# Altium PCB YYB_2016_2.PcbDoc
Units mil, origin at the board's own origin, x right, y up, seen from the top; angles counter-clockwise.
Board outline 590 x 11950 mil, 2 copper layers (Top Layer, Bottom Layer); 76 components, 58 nets, 220 pads, 97 vias.
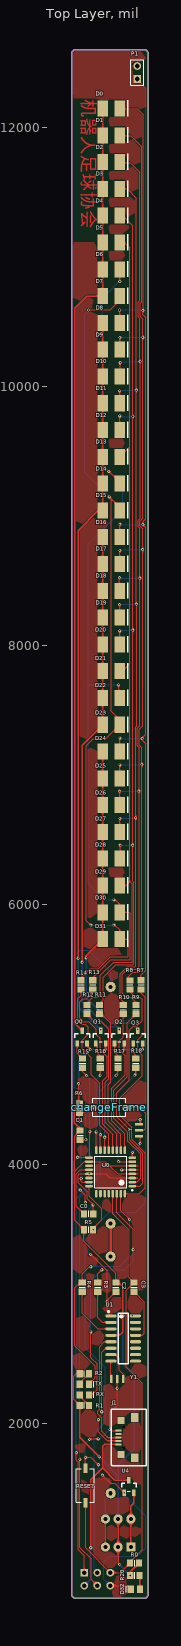
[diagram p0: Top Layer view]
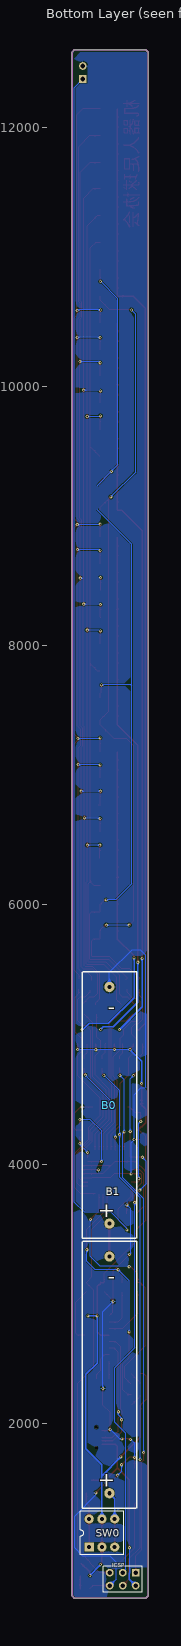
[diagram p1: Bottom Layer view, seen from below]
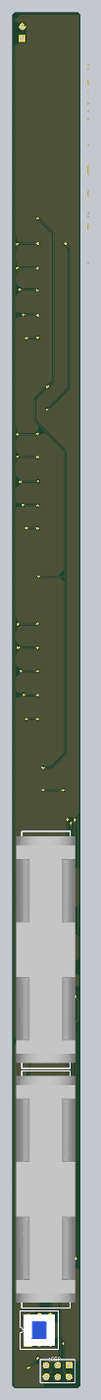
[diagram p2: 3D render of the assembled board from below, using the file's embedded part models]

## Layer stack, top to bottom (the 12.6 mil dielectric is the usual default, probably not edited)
Top Solder: solder mask 0.4, Solder Resist, Dk 3.5
Top Layer: signal copper 1.4
Dielectric 1: dielectric 12.6, FR-4, Dk 4.8
Bottom Layer: signal copper 1.4
Bottom Solder: solder mask 0.4, Solder Resist, Dk 3.5

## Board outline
4930,670 4930,12580 4950,12600 5500,12600 5520,12580 5520,670 5500,650 4950,650

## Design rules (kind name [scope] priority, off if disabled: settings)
Clearance [All] p1: gap=7
PolygonConnect [All] p1: connectstyle=Relief reliefconductorwidth=10 reliefentries=4 polygonreliefangle="90 Angle" airgapwidth=10
RoutingVias [All] p1: holewidth=11.81 width=31.5 viastyle="Through Hole" minholewidth=11.81 minwidth=23.62 maxholewidth=248.03 maxwidth=50
SolderMaskExpansion [All] p1: expansion=4
Width [All] p1: maxlimit=30 minlimit=6 preferedwidth=10
30 further rules are at their usual default settings.

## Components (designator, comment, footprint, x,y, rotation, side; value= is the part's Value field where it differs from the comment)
B0 "Battery" BAT 5230,4470 r0 bottom locked
B1 "Battery" BAT 5230,2389 r0 bottom locked
C0 "" 6-0805_N 5060,3616 r180 top
C1 "Cap" 6-0805_N 4994,4224 r90 top
C2 "Cap" 6-0805_N 5270,3050 r90 top
C3 "Cap" 6-0805_N 5410,3050 r90 top
changeFrame "SW-PB" KEY_SODFL_2-LEADS 5220,4440 r180 top
D0 "" LED_3528 5234.06,12146.77 r0 top
D1 "" LED_3528 5234.06,11940 r0 top
D2 "" LED_3528 5234.06,11733.23 r0 top
D3 "" LED_3528 5234.06,11526.45 r0 top
D4 "" LED_3528 5234.06,11319.68 r0 top
D5 "" LED_3528 5234.06,11112.9 r0 top
D6 "" LED_3528 5234.06,10906.13 r0 top
D7 "" LED_3528 5234.06,10699.36 r0 top
D8 "" LED_3528 5234.06,10492.58 r0 top
D9 "" LED_3528 5234.06,10285.81 r0 top
D10 "" LED_3528 5234.06,10079.03 r0 top
D11 "" LED_3528 5234.06,9872.26 r0 top
D12 "" LED_3528 5234.06,9665.48 r0 top
D13 "" LED_3528 5234.06,9458.71 r0 top
D14 "" LED_3528 5234.06,9251.94 r0 top
D15 "" LED_3528 5234.06,9045.16 r0 top
D16 "" LED_3528 5234.06,8838.39 r0 top
D17 "" LED_3528 5234.06,8631.61 r0 top
D18 "" LED_3528 5234.06,8424.84 r0 top
D19 "" LED_3528 5234.06,8218.07 r0 top
D20 "" LED_3528 5234.06,8011.29 r0 top
D21 "" LED_3528 5234.06,7804.52 r0 top
D22 "" LED_3528 5234.06,7597.74 r0 top
D23 "" LED_3528 5234.06,7390.97 r0 top
D24 "" LED_3528 5234.06,7184.2 r0 top
D25 "" LED_3528 5234.06,6977.42 r0 top
D26 "" LED_3528 5234.06,6770.65 r0 top
D27 "" LED_3528 5234.06,6563.87 r0 top
D28 "" LED_3528 5234.06,6357.1 r0 top
D29 "" LED_3528 5234.06,6150.33 r0 top
D30 "" LED_3528 5234.06,5943.55 r0 top
D31 "" LED_3528 5234.06,5736.78 r0 top
D32 "LED" LED_0805 5420.37,719 r180 top
ICSP "ICSP" HDR2X3 5027,847 r0 bottom
J1 "USB_MINI" MICRO_USB 5290,1890 r90 top
P1 "Header 2" HDR1X2 5435,12375 r90 top
Q0 "PNP" PNP_SOT_23 5010,4980 r270 top
Q1 "PNP" PNP_SOT_23 5153.33,4980 r270 top
Q2 "PNP" PNP_SOT_23 5296.67,4980 r270 top
Q3 "PNP" PNP_SOT_23 5440,4980 r270 top
R0 "" 6-0805_N 5414,921 r180 top
R1 "Res1" 6-0805_N 5027,2138 r0 top
R2 "Res1" 6-0805_N 5027,2382 r0 top
R3 "Res1" 6-0805_N 5130,3050 r270 top
R4 "Res1" 6-0805_N 5010,3050 r270 top
R5 "Res1" 6-0805_N 5059,3493 r180 top
R6 "Res1" 6-0805_N 4988,4432 r90 top
R7 "Res1" 6-0805_N 5465,5384 r270 top
R8 "Res1" 6-0805_N 5378,5383 r270 top
R9 "Res1" 6-0805_N 5425,5193 r270 top
R10 "Res1" 6-0805_N 5327,5193 r270 top
R11 "Res1" 6-0805_N 5145,5193 r270 top
R12 "Res1" 6-0805_N 5047,5193 r270 top
R13 "Res1" 6-0805_N 5092,5384 r270 top
R14 "Res1" 6-0805_N 5001,5384 r270 top
R15 "Res1" 6-0805_N 5012,4779 r270 top
R16 "Res1" 6-0805_N 5149,4779 r270 top
R17 "Res1" 6-0805_N 5286,4779 r270 top
R18 "Res1" 6-0805_N 5423,4779 r270 top
R20 "Res1" 6-0805_N 5416.43,825 r180 top
RESET "SW-PB" KEY_SODFL_2-LEADS 5035,1520 r270 top
RX "" LED_0805 5027,2219 r0 top
SW0 "SelfLockSW" KEY_ZS_8*8 5317,1153 r90 bottom
TX "" LED_0805 5027,2301 r0 top
U0 "ATMEL328P" "TQFP 32" 5230,3940 r180 top
U1 "CH340B" SOP16 5350,2530 r0 top
U4 "SC662K" SOT-23 5371,1512 r270 top
Y "8M" XTAL 5471,4262 r0 top
Y1 "12M" XTAL 5280,2319 r270 top

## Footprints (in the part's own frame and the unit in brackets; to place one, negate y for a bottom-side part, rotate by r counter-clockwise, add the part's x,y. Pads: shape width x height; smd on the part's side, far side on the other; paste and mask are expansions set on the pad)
6-0805_N [mm] "Chip Resistor, Body 2.0x1.2mm, IPC Medium Density"
  rect 1.2x1.4 smd: 1(-0.9,0) 2(0.9,0)
  silkscreen extent 0,-0.6 0,0.6, body extent -1.07,-0.7 1.07,0.7, height 0.7
BAT [mm]
  round 2 hole 0.8: 1(0,23.6) 2(0,-22.8)
  silkscreen extent -5.4,-25.8 5.3,26.5, body extent -6.5,-24.7 6.5,25.3, height 13.75
HDR1X2 [mm] "Connector; Header; 2 Position"
  rect 1.5x1.5 hole 0.9: 1(0,0)
  round 1.5 hole 0.9: 2(2.54,0)
  silkscreen extent -1.27,-1.27 3.81,1.27
HDR2X3 [mm] "Connector; Header; 3x2 Position"
  rect 1.5x1.5 hole 0.9: 1(0,0)
  round 1.5 hole 0.9: 2(0,2.54) 3(2.54,0) 4(2.54,2.54) 5(5.08,0) 6(5.08,2.54)
  silkscreen extent -1.27,-1.27 6.35,3.81
KEY_SODFL_2-LEADS [mm] "SODFL, 2-Leads, Body 3.25x8.00mm, IPC Medium Density"
  rect 1.85x0.85 smd: 1(-3.375,0) 2(3.375,0)
  silkscreen extent -3.25,-1.75 3.25,1.75, body extent -4,-1.8 4,1.91, height 2.5
KEY_ZS_8*8 [mm]
  rect 1.8x1.8 hole 0.8: 1(-2.75,1.75)
  round 1.8 hole 0.8: 2(-2.75,-0.75) 3(-2.75,-3.25) 4(2.75,-3.25) 5(2.75,-0.75) 6(2.75,1.75)
  silkscreen extent -4.25,-5 4.25,3.5, body extent -3.5,-4.26 3.5,2.74, height 13
LED_0805 [mm] "Chip LED  Body 2.0x1.2mm, IPC Medium Density"
  rect 1.2x1.4 smd: 1(-0.9,0) 2(0.9,0)
  silkscreen extent 1.8,-0.6 1.8,0.6, body extent -1.07,-0.7 1.07,0.7, height 0.7
LED_3528 [mm] "Chip Diode, 2-Leads, Body 5.00x3.00mm, IPC Medium Density"
  rect 2x3.15 smd: 1(-1.675,0) 2(1.675,0)
  silkscreen extent 3.2,-1.5 3.2,1.6, body extent -2.5,-1.5 2.5,1.5, height 2
MICRO_USB [mm]
  round 0.5 hole 0.5: 0(-2.032,-1.016) 0(2.032,-1.016)
  rect 0.4x1.2 smd: 1(-1.333,0) 2(-0.667,0) 3(0,0) 4(0.667,0) 5(1.333,0)
  rect 1.4x1.4 smd: 6(-3.302,-0.508) 7(3.302,-0.508)
  rect 1.7x1.5 smd: 8(-3.937,-3.175) 9(3.937,-3.175)
  silkscreen extent -5.54,-5.46 5.59,1.4, body extent -4.4,-5.72 4.4,0.02, height 2.71
PNP_SOT_23 [mm]
  rect 1.25x0.7 smd: 1(1.25,-0.95) 2(1.25,0.95) 3(-1.25,0)
  silkscreen extent -0.65,-1.46 0.9,1.46, body extent -1.5,-1.5 1.5,1.5, height 1.3
SOP16 [mm] "CH340G"
  oval 2.2x0.6 smd: 1(-3,7.595) 2(-3,6.325) 3(-3,5.055) 4(-3,3.785) 5(-3,2.515) 6(-3,1.245) 7(-3,-0.025) 8(-3,-1.295) 9(1.8,-1.295) 10(1.8,-0.025) 11(1.8,1.245) 12(1.8,2.515) 13(1.8,3.785) 14(1.8,5.055) 15(1.8,6.325) 16(1.8,7.595)
  silkscreen extent -3.65,-1.83 0.4,8.6, body extent -3.68,-1.78 2.51,8.13, height 1.7
SOT-23 [mm]
  rect 1.25x0.7 smd: 1(1.25,-0.95) 2(1.25,0.95) 3(-1.25,0)
  silkscreen extent -0.65,-1.46 0.9,1.46, body extent -1.5,-1.5 1.5,1.5, height 1.3
"TQFP 32" [mm] "ATMEL 328P"
  oval 1.5x0.5 smd: 1(-4.25,2.8) 2(-4.25,2) 3(-4.25,1.2) 4(-4.25,0.4) 5(-4.25,-0.4) 6(-4.25,-1.2) 7(-4.25,-2) 8(-4.25,-2.8) 17(4.25,-2.8) 18(4.25,-2) 19(4.25,-1.2) 20(4.25,-0.4) 21(4.25,0.4) 22(4.25,1.2) 23(4.25,2) 24(4.25,2.8)
  oval 0.5x1.5 smd: 9(-2.8,-4.25) 10(-2,-4.25) 11(-1.2,-4.25) 12(-0.4,-4.25) 13(0.4,-4.25) 14(1.2,-4.25) 15(2,-4.25) 16(2.8,-4.25) 25(2.8,4.25) 26(2,4.25) 27(1.2,4.25) 28(0.4,4.25) 29(-0.4,4.25) 30(-1.2,4.25) 31(-2,4.25) 32(-2.8,4.25)
  silkscreen extent -4.38,-3.1 3.1,3.72, body extent -4.57,-4.57 4.57,4.57, height 1.62
XTAL [mm] "Chip Array, ConvexE, 6-Leads, Pitch 1.20mm,  Body 3.20x1.50mm,  IPC Medium Density"
  rect 1.6x0.5 smd: 1(-0.6,1.2) 2(-0.6,0) 3(-0.6,-1.2)

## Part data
C0: library part Cap, "Capacitor"
C1 C2 C3: "Capacitor"
changeFrame RESET: "Switch"
D0 D1 D2 D3 D4 D5 D6 D7 D8 D9 D10 D11 D12 D13 D14 D15 D16 D17 D18 D19 D20 D21 D22 D23 D24 D25 D26 D27 D28 D29 D30 D31 RX TX: library part LED
P1: "Header, 2-Pin"
Q0 Q1 Q2 Q3: "PNP Transistor"
R0: library part Res1, "Resistor"
R1 R2 R3 R4 R5 R6 R7 R8 R9 R10 R11 R12 R13 R14 R15 R16 R17 R18 R20: "Resistor"
SW0: library part SelfLockSwitch, "自锁开关"
U0: library part ATMEL-328P
U1: "usb to uart"
U4: library part SC662k-3.3V, "3.3V 稳压芯片"
Y Y1: library part XTAL

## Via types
v1: diameter 23.62, hole 11.81, Top Layer to Bottom Layer, 97 vias

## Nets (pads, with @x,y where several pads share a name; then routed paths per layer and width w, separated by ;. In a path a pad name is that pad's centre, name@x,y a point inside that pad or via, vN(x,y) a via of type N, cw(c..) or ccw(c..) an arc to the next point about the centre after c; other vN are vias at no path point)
3.3V: C1.2 C2.2 Q0.2 Q1.2 Q2.2 Q3.2 R0.1 R1.1 R2.1 R5.2 R6.2 R20.2 SW0.2 SW0.5 U0.4 U0.6 U0.18 U1.4 U1.16 | length 7258.4
  Top Layer w7: R1.1 4945.5,2184.07 4945.5,2363.5 4964,2382 R2.1 ; C1.2 4951,4216.43 4951,3945 ; C2.2 5270,3159 5023.57,3405.43 R5.2 4951,3565.57 4951,3945 ; 5441,3986 5439.76,3987.24 U0.6 5219.76,3987.24 ; 5443,3925 5442.25,3924.25 U0.4 5282.75,3924.25 5219.76,3987.24 ; 4951,3945 5024.74,4018.74 U0.18 5188.26,4018.74 5219.76,3987.24
  Top Layer w10: R6.2@4970.43,4467.43 4990.72,4467.43 4948.44,4425.16 4948.44,4320.56 5005.57,4263.43 C1.2@5018,4263.43 ; v1(4982,4622) 4982,4481.43 4978,4477.43 R6.2 ; R1.1 4991.57,1890.43 v1(5142,1740) ; Q0.2 5047.4,4912.6 5071,4889 v1(5071,4884) ; v1(5190.73,4885.27) Q1.2 ; U1.4 5297.02,2679.02 5322,2704 5322,3056 5292.57,3085.43 C2.2 ; SW0.5 SW0.2 5287.47,921.53 v1(5299,910) ; v1(5334.07,4882.93) Q2.2 ; v1(5381,825) 5381,852.57 R0.1 ; v1(5475,4884) 5475,4928.39 Q3.2
  Bottom Layer w10: v1(4982,4622) 4982,4795 v1(5071,4884) v1(5475,4884) ; v1(5142,1740) 5287.47,1591.53 ; SW0.5@5287.47,1258.27 5287.47,1591.53 ; v1(5299,910) 5299,907 v1(5381,825) ; v1(5396,2829) 5325,2829 v1(5324,2828) 5324,2464 5411,2377 5411,1804 5287.47,1680.47 5287.47,1591.53
A0: changeFrame.2 R6.1 U0.23 | length 719.3
  Top Layer w7: v1(4988,4330) R6.1 5030.57,4396.57 5074,4440 changeFrame.2 ; v1@4998,3882 4998,3873 5009.74,3861.26 U0.23
  Bottom Layer w7: v1(4988,4330) 5004,4314 5004,3888 v1@4998,3882
  other v1: 5003,3889
A1: P1.1 R5.1 U0.24 | length 9603.3
  Top Layer w7: U0.24 5062.68,3753.32 5161,3655 5161,3572 5094.43,3505.43 v1(5094.43,3493)
  Bottom Layer w7: v1(5094.43,3493) 5094.43,3505.43 5217,3628 5422,3628 5501.5,3707.5 5501.5,12308.5 P1.1
A2: U0.25
A3: U0.26
A4: U0.27
A5: U0.28
A6: U0.19
A7: U0.22
D0/RXD: R3.1 RX.2 U0.30 | length 2015.7
  Top Layer w7: RX.2 5085,2219 5125,2259 5125,2458 5077,2506 v1(5077,2705) ; R3.1 5130,3153 v1(5162,3185) ; U0.30 5277.24,3624.76 5403,3499 v1(5403,3339)
  Bottom Layer w7: v1(5077,2705) 5077,3100 v1(5162,3185) 5338,3185 5403,3250 v1(5403,3339)
D1/TXD: R4.1 TX.2 U0.31 | length 1922.8
  Top Layer w7: TX.2 5111,2349.57 5111,2441 4953,2599 4953,3045 4993.43,3085.43 R4.1 5010,3153 5065,3208 v1(5077,3208) ; U0.31 5309,3772.42 5309,3640 v1(5376,3573)
  Bottom Layer w7: v1(5077,3208) 5071.5,3208 5068.25,3211.25 5299.25,3211.25 5376,3288 v1(5376,3573)
D2: R7.2 U0.32 | length 1911.8
  Top Layer w7: U0.32 5450.68,3772.68 5497,3819 5497,4085 5391,4191 5391,4284 5299,4376 5299,4507 5474,4682 5474,4840 5437,4877 5437,4959 5495,5017 5495,5287 5465,5317 R7.2
D3: R8.2 U0.1 | length 1826.3
  Top Layer w7: R8.2 5378,5332 5421,5289 5455,5289 5473,5271 5473,5106 5436,5069 5407,5069 5372,5034 5372,4965.89 5373,4964.89 5373,4646 5277.14,4550.14 5277.14,4363.86 5377,4264 5377,4185.2 5478,4084.2 5478,3853 5454.76,3829.76 U0.1
D4: R9.2 U0.2 | length 1497.7
  Top Layer w7: R9.2 5358,5090.57 5358,4960.09 5358.35,4959.74 5358.35,4674.35 5255.29,4571.29 5255.29,4354 5255.5,4353.5 5363,4246 5363,4177 5461,4079 5461,3892 5430.26,3861.26
  Top Layer w10: U0.2 5430.26,3861.26
D5: R10.2 U0.9 | length 1168.8
  Top Layer w7: R10.2 5327,4981 5298,4952 5298,4881 5341,4838 5341,4688 5233.44,4580.44 5233.5,4340.5 5340.24,4233.76 U0.9
D6: R11.2 U0.10 | length 1141.8
  Top Layer w7: R11.2 5159.43,5157.57 5230,5087 5230,4631 5211.57,4612.57 5211.57,4329.43 5308.74,4232.26 U0.10
D7: R12.2 U0.11 | length 1198.1
  Top Layer w7: R12.2 5049.23,5157.57 5104.8,5102 5155,5102 5216,5041 5216,4657 5189.71,4630.71 5189.71,4323.29 5277.24,4235.76 U0.11
D8: R13.2 U0.12 | length 1456.5
  Top Layer w7: R13.2 5092,5325 5045,5278 5016,5278 4992,5254 4992,5127 5020,5099 5060,5099 5118,5041 5118,5000 5148,4970 5148,4883 5202,4829 5202,4679 5167.86,4644.86 5167.86,4307.14 5245.75,4229.25 U0.12
D9: R14.2 U0.13 | length 1404.1
  Top Layer w7: R14.2 5001,5303 4974,5276 4974,5118 5012,5080 5035,5080 5057,5058 5057,5002 5011,4956 5011,4891 5035,4867 5036,4867 5081,4822 5081,4690 5146,4625 5146,4300 5214.25,4231.75 U0.13
D10: R18.2 U0.14 | length 735.8
  Top Layer w7: U0.14 5184,4108.57 v1(5184,4208) ; v1(5416,4687) 5423,4694 R18.2
  Bottom Layer w7: v1(5184,4208) 5184,4455 v1(5416,4687)
D11/MOSI: ICSP.4 R17.2 U0.15 | length 4294.9
  Top Layer w7: v1(4993,1721) 4993,1041 5079,955 5079,795 ICSP.4 ; v1(5151,4227) 5151,4111.58 5149,4109.58 U0.15 ; v1(5272,4684) 5286,4698 R17.2
  Bottom Layer w7: v1(4993,1721) 4993,3740 5151,3898 v1(5151,4227) 5151,4566 5150,4567 5266,4683 v1@5266.77,4685.57
D12/MISO: ICSP.1 R16.2 U0.16 | length 4149.6
  Top Layer w7: v1(4966,1773) 4966,1716.45 4979,1703.45 4979,1024 5027,976 ICSP.1 ; v1(5117,4249) 5117,4110.09 U0.16 ; v1(5149,4685) R16.2
  Bottom Layer w7: v1(4966,1773) 4965,1774 4965,3731.88 5127,3893.88 5127,4239 v1(5117,4249) 5117,4653 v1(5149,4685)
D13/SCK: ICSP.3 R15.2 U0.17 | length 4178
  Top Layer w7: v1(4975,4053) 5057.44,4053 5061.44,4049 U0.17 5069,4056.56 v1(5069,4253) ; v1(4995,3799) 5034.5,3759.5 v1(5034.5,3702.5) ; R15.2 5012,4715 v1(5044,4683)
  Bottom Layer w7: v1@4980,4053 v1(4975,4053) 4945.5,4023.5 4945.5,3848.5 v1(4995,3799) ; v1(5034.5,3702.5) 5033.75,3701.75 5033.75,2583.25 5189,2428 5189,2007 5105,1923 5105,869 ICSP.3 ; v1(5044,4683) 5069,4658 v1(5069,4253)
GND: B0.2 C0.1 C1.1 C2.1 changeFrame.1 D32.2 ICSP.6 J1.5 P1.2 RESET.1 U0.3 U0.5 U0.21 U1.1 U4.1 Y1.2 Y.2 | length 7891.9
  Top Layer w7: C1.1 5037.57,4188.57 v1(5039,4190) ; RESET.1 v1(5035,1737) 5078,1737 v1(5135,1680) ; v1(5068,1875) 5072,1879 v1(5134,1879) ; v1(5074.55,3304) 5202,3176.55 v1(5202,2940) ; C0.1 5095.43,3687.57 5048.68,3734.32 5048.68,3787.32 4979,3857 4979,3914 4989,3924 5018,3924 5018.25,3924.25 U0.21 5192.75,3924.25 5224,3893 5365,3893 5365.24,3892.76 U0.3 5440.76,3892.76 5441,3893 ; v1(5166.5,1599.5) 5230,1536 5260.39,1536 v1(5333.6,1462.79) ; ICSP.6 5356.94,747 D32.2 ; U1.1 5204,2856.91 5204,2948.57 C2.1 ; Y1.2 v1(5280,2269) 5280,2140 5224,2084 v1(5224,1953) 5225,1953 5235.5,1942.5 J1.5 ; v1@5314,3957 v1(5315.25,3955.75) U0.5 5442.75,3955.75 ; changeFrame.1 v1(5441,4440) 5456,4440 5501.5,4394.5 5501.5,4278.5 5485,4262 Y.2
  Bottom Layer w7: v1(5035,1737) 5035,1845 v1@5060,1870 ; v1(5063,3924) 5063,4166 v1(5039,4190) 5039,4535 4990,4584 4960,4584 4949,4595 4949,5611.5 4989.5,5652 5059,5652 5230,5481 B0.2 ; v1(5074.55,3304) 5064,3314.55 5064,3654 v1(5095,3685) ; v1(5134,1879) 5150,1879 v1(5224,1953) ; v1(5135,1680) 5135,1631 v1(5166.5,1599.5) ; v1(5202,2940) 5280,2862 v1(5280,2269) ; ICSP.6 5178,796 5178,927 5225,974 5435,974 5499,1038 5499,1283 5333.6,1448.4 v1(5333.6,1462.79)
LED0: D0.2 D8.2 D16.2 D24.2 R7.1 | length 7785.2
  Top Layer w7: v1(5298,10592) 5300,10590 D8.2 ; D24.2 v1@5300,7289 ; D16.2 5301,8839.39 v1(5301,8939) ; D0.2 5434.23,12146.77 5482,12099 5482,10590 v1(5479,10587) 5479,10556 5501.5,10533.5 5501.5,8979.5 5478,8956 v1(5478,8935) 5501.5,8911.5 5501.5,8881 5501.5,7319.5 5473,7291 v1(5473,7284) 5473,7272.25 5501.5,7243.75 5501.5,5495.5 5463,5457 R7.1@5463,5427.43
  Bottom Layer w7: v1(5298,10592) 5474,10592 v1(5479,10587) ; v1(5301,7290) 5307,7284 v1(5473,7284) ; v1(5301,8939) 5305,8935 v1(5478,8935)
LED1: D1.2 D9.2 D17.2 D25.2 R8.1 | length 7588.6
  Top Layer w7: D25.2 5301,6978.42 v1(5301,7081) ; D17.2 5301,8632.61 v1(5301,8736) ; D9.2 5300,10378 v1(5301,10379) ; D1.2 5305,11935 5385,11935 5468,11852 5468,10657.2 5456.69,10645.89 5456.69,10544.31 5479.31,10521.69 5479.31,8985.31 5455.69,8961.69 5455.69,8925.76 5477,8904.45 5477,7384 5450.69,7357.69 5450.69,7234.31 5471,7214 v1(5471,7083) 5471,5506 5445,5480 5400,5480 5366,5446 R8.1@5366,5419.43
  Bottom Layer w7: v1(5301,7081) 5303,7083 v1(5471,7083) ; v1(5301,8736) 5307,8742 v1(5477,8742) ; v1@5301,10380 v1(5479,10380)
LED2: D2.2 D10.2 D18.2 D26.2 R9.1 | length 7606.6
  Top Layer w7: v1(5297,8527) 5297,8427.84 D18.2 ; v1(5299,6878) 5299,6771.65 D26.2 D26.2@5314.35,6770.65 ; D10.2 5302,10081.03 v1(5302,10185) ; D2.2 5305.23,11728 5381,11728 5454,11655 5454,10663 5442.69,10651.69 5442.69,10538.51 5456,10525.2 5456,10195 v1(5457,10194) 5457,8982.8 5441.69,8967.49 5441.69,8919.96 5454.69,8906.96 5454.69,7381.69 5436.69,7363.69 5436.69,7228.51 5448.69,7216.51 5448.69,5522.69 5429,5503 5357,5503 5321,5467 5321,5317 5350,5288 5384.16,5288 R9.1@5438,5234.16
  Bottom Layer w7: v1(5297,8527) 5300,8524 5301,8525 5303,8523 v1(5454.69,8523) ; v1(5299,6878) v1(5448,6878) ; v1(5302,10185) 5312,10195 5313,10194 v1(5457,10194)
LED3: D3.2 D11.2 D19.2 D27.2 R10.1 | length 7180.9
  Top Layer w7: v1(5299,8318) 5299,8219.07 D19.2 ; v1(5299,9968) 5300,9967 D11.2 ; D27.2 5301,6564.87 v1(5301,6668) ; D3.2 5357.55,11526.45 5428.69,11455.31 v1(5428.69,9973.31) 5427.69,9972.31 v1(5427.69,8321.31) 5422.69,8316.31 5430,8309 5430,7381 5422.69,7373.69 5422.69,5531.69 5414,5523 5357,5523 5305,5471 5305,5275 5335,5245 R10.1@5335,5228.43
  Bottom Layer w7: v1@5295,8322 v1(5299,8318) 5302.31,8321.31 v1(5427.69,8321.31) ; v1(5299,9968) 5304.31,9973.31 v1(5428.69,9973.31) ; v1(5301,6668) 5418,6668 v1(5423,6673)
LED4: D4.2 D12.2 D20.2 D28.2 R11.1 | length 6962.2
  Top Layer w7: R11.1@5135.43,5231.43 5173,5269 5173,5444 5268,5539 5399.58,5539 5408.69,5548.11 5408.69,6175.31 5400.69,6183.31 5400.69,8121.69 v1(5401,8122) v1(5401,9770) 5401,11243 5324.32,11319.68 D4.2 ; D28.2 5303,6360.1 v1(5303,6462) ; D20.2 v1(5300,8116) ; D12.2 v1(5300,9775)
  Bottom Layer w7: v1(5300,9775) 5305,9770 v1(5401,9770) ; v1@5301,8117 5303,8115 5310,8122 v1(5401,8122) ; v1(5303,6462) v1(5400,6462)
LED5: D5.2 D13.2 D21.2 D29.2 R12.1 | length 6498.6
  Top Layer w7: R12.1@5029,5227 5090,5288 5127,5288 5151,5312 5151,5456.33 5252.67,5558 5393,5558 5394.69,5559.69 5394.69,6163.31 5377,6181 ; D29.2 5346.33,6150.33 5377,6181 ; D21.2 5319.52,7804.52 5377,7862 ; D13.2 5376,9534.71 5376,11072 5335.1,11112.9 D5.2 ; 5377,9534.71 5377,8129.55 5377,7862 ; 5377,6181 5377,7862
LED6: D6.2 D14.2 D22.2 D30.2 R13.1 | length 6856.4
  Top Layer w7: R13.1@5106,5419.43 5092,5433.43 5092,5439 5231,5578 5379,5578 5380.69,5579.69 5380.69,5932.31 5369.45,5943.55 D30.2 5300,6004 5264,6040 v1(5255,6040) ; v1(5215,9347) 5300,9262 D14.2 ; v1(5291,7699) 5291,7643 5300,7634 D22.2 ; v1(5300,10812) D6.2
  Bottom Layer w7: v1@5255,6039 5181,6039 5058,6162 5058,7693 5064,7699 v1(5291,7699) 5058,7699 5058,8785 5325,9052 5325,9237 v1(5215,9347) 5164,9398 5164,10680 5296,10812 v1(5300,10812)
LED7: D7.2 D15.2 D23.2 D31.2 R14.1 | length 6428.9
  Top Layer w7: R14.1@5011,5419.43 5001,5429.43 5001,5438 5071,5508 5133.33,5508 5225.33,5600 5363,5600 5366.69,5603.69 5366.69,5724.31 5354.22,5736.78 D31.2 5300,5807 5262,5845 v1(5254,5845) ; v1(5060,10592) 5060,10593 5062,10595 5226,10595 5300,10669 D7.2 ; v1(5077,5844) 5077,5845 5043,5879 5043,7230 5097,7284 5193.03,7284 D23.2 5300,7431 5234.5,7496.5 5234.5,9134.5 ; v1(5219,9150) 5234.5,9134.5 ; D15.2 5300,9069 5234.5,9134.5
  Bottom Layer w7: v1(5060,10592) 5028,10560 5028,9341 v1(5219,9150) ; v1(5077,5844) 5253,5844 v1(5254,5845)
NetB0_1: B0.1 B1.2 | length 245.4
  Top Layer w20: B1.2@5230,3295.51 B0.1
NetB1_1: B1.1 SW0.3 SW0.4 | length 432.1
  Top Layer w10: SW0.3 SW0.4
  Bottom Layer w10: SW0.4 5189.05,1418.91 B1.1
NetC0_2: C0.2 U0.20 | length 443.5
  Top Layer w7: C0.2 4965,3675.57 4965,3924 4996.75,3955.75 U0.20
NetC3_1: C3.1 U1.13 | length 427
  Top Layer w7: C3.1 5489,2935.57 5489,2695 5473.02,2679.02 U1.13
NetD0_1: D0.1 D1.1 D2.1 D3.1 D4.1 D5.1 D6.1 D7.1 Q0.3 | length 7303.4
  Top Layer w10: Q0.3 4952.21,5087 4952.21,10607.21 5044.36,10699.36 D7.1 D6.1 D5.1 D4.1 D3.1 D2.1 D1.1 D0.1
NetD8_1: D8.1 D9.1 D10.1 D11.1 D12.1 D13.1 D14.1 D15.1 Q1.3 | length 5880
  Top Layer w10: v1(4978,5588) 4978,8888 5135.16,9045.16 D15.1 D14.1 D13.1 D12.1 D11.1 D10.1 D9.1 D8.1
  Bottom Layer w10: v1(4978,5588) 4978,5212 4980,5210 ; v1(5153,5038) v1@5155,5035 ; 4980,5210 5152.5,5037.5 v1@5155,5035 ; 4980,5210 v1@5155,5035
NetD16_1: D16.1 D17.1 D18.1 D19.1 D20.1 D21.1 D22.1 D23.1 Q2.3 | length 4029.4
  Top Layer w10: v1(5010,5558) 5010,7232.86 D23.1 D22.1 D21.1 D20.1 D19.1 D18.1 D17.1 D16.1
  Bottom Layer w10: v1(5010,5558) 5010,5248 5198.5,5059.5 5276.5,5059.5 v1(5297,5039)
NetD24_1: D24.1 D25.1 D26.1 D27.1 D28.1 D29.1 D30.1 D31.1 Q3.3 | length 2460.8
  Top Layer w10: v1(5040,5591) 5040,5608.67 5051.33,5620 D31.1 D30.1 D29.1 D28.1 D27.1 D26.1 D25.1 D24.1
  Bottom Layer w10: v1(5040,5591) 5040,5285 5237,5088 5387,5088 5440,5035 v1(5440,5040)
NetD32_1: D32.1 R20.1 | length 107.6
  Top Layer w10: R20.1 5455.8,821.06 D32.1
NetQ0_1: Q0.1 R15.1 | length 132.7
  Top Layer w7: Q0.1 4972.6,4853.84 R15.1
NetQ1_1: Q1.1 R16.1 | length 125.2
  Top Layer w7: Q1.1@5127.6,4930.79 5127.6,4859.4 5149,4838 R16.1
NetQ2_1: Q2.1 R17.1 | length 129.4
  Top Layer w7: Q2.1 5262.6,4930.79 5262.6,4864.4 5286,4841 R17.1
NetQ3_1: Q3.1 R18.1 | length 124.8
  Top Layer w7: Q3.1 5402.6,4859.4 5423,4839 R18.1
NetR1_2: R1.2 RX.1 | length 110.4
  Top Layer w7: RX.1 4991.57,2208.87 R1.2
NetR2_2: R2.2 TX.1 | length 110.4
  Top Layer w7: TX.1 4991.57,2311.13 R2.2
NetR3_2: R3.2 U1.2 | length 317.5
  Top Layer w7: R3.2 5130,2813 5163.98,2779.02 U1.2
NetR4_2: R4.2 U1.3 | length 437.7
  Top Layer w7: R4.2 5010,2848 5128.98,2729.02 U1.3
NetSW0_1: SW0.1 SW0.6 U4.2 | length 427.4
  Top Layer w10: SW0.1 SW0.6 5385.9,1359.9 5408.4,1382.4 U4.2
NetU0_7: U0.7 Y.1 | length 586.1
  Top Layer w7: v1(5290.26,4018.74) U0.7 ; Y.1@5457.38,4306.24 5458,4306.87 v1(5458,4343)
  Bottom Layer w7: v1(5290.26,4018.74) 5290.26,4256.26 5378,4344 5443,4344 5444,4343 v1(5458,4343)
NetU0_8: U0.8 Y.3 | length 190.5
  Top Layer w7: U0.8 5398,4050.91 v1(5398,4090) ; v1(5457,4159) 5457.38,4159.38 Y.3@5457.38,4211.76
  Bottom Layer w7: v1(5398,4090) 5462,4154 v1(5457,4159)
NetU1_7: U1.7 Y1.1 | length 246.4
  Top Layer w7: U1.7 5266.98,2529.02 5298,2498 5298,2408 5327.24,2378.76 Y1.1
NetU1_8: U1.8 Y1.3 | length 140.1
  Top Layer w7: U1.8 5231.89,2340.89 Y1.3
RESET: C3.2 ICSP.5 R0.2 RESET.2 U0.29 | length 3840.2
  Top Layer w7: RESET.2@5028,1387.13 5036,1379.13 5036,1038 ICSP.5 5304.57,847 R0.2 5378.57,927.57 5475,1024 5475,2309 5351,2433 5351,3026.43 C3.2 5366,3129.43 5366,3497 5245.75,3617.25 U0.29
UD+: J1.3 U1.5 | length 925.6
  Top Layer w7: 5209,1890 5161,1938 5161,2041 5129,2073 5129,2094.55 5144,2109.55 5144,2592 5181.02,2629.02 U1.5
  Top Layer w10: 5209,1890 J1.3
UD-: J1.2 U1.6 | length 893.2
  Top Layer w7: v1(5135,2027) 5135,1934 5205.25,1863.75 ; v1(5161,2089) 5161,2549 5191.02,2579.02 U1.6
  Top Layer w10: 5205.25,1863.75 J1.2
  Bottom Layer w7: v1(5135,2027) 5135,2038 5161,2064 v1(5161,2089)
USB_5V: ICSP.2 J1.1 U4.3 | length 1512.2
  Top Layer w10: v1(5076,1039) 5076,1565 5169,1658 5169,1823 5183.5,1837.5 J1.1 ; 5167,1656 5261.79,1561.21 U4.3
  Bottom Layer w10: ICSP.2 5075.47,795.47 5075.47,847.52 ; 5074,841 5074,1037 v1(5076,1039)
pads on no net: J1.0 J1.4 J1.6 J1.7 J1.8 J1.9 U1.9 U1.10 U1.11 U1.12 U1.14 U1.15

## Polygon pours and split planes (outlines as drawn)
GND on Bottom Layer "GND" (solid, pour order 14): 4930,12580 5514,12580 5517,12583 5517,667 5517,657 5502,642 5494,650 4950,650 4930,670
GND on Top Layer "GND" (solid, pour order 16): 5517,667 5503,653 5485,653 4947,653 4930,670 4927,673 4927,12589 5506,12589 5517,12600

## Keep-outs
Keep-Out Layer:
  lines w10: 4930,670 4930,1020 4930,12580 4950,12600 5500,12600 5517,12583 5517,667 5500,650 4950,650 4930,670

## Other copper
Top Layer:
  text "机器人足球协会" at 4974,12218 h177.17 r270

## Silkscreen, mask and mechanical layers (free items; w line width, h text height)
Top Solder:
  text "机器人足球协会" at 4974,12218 h177.17 r270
